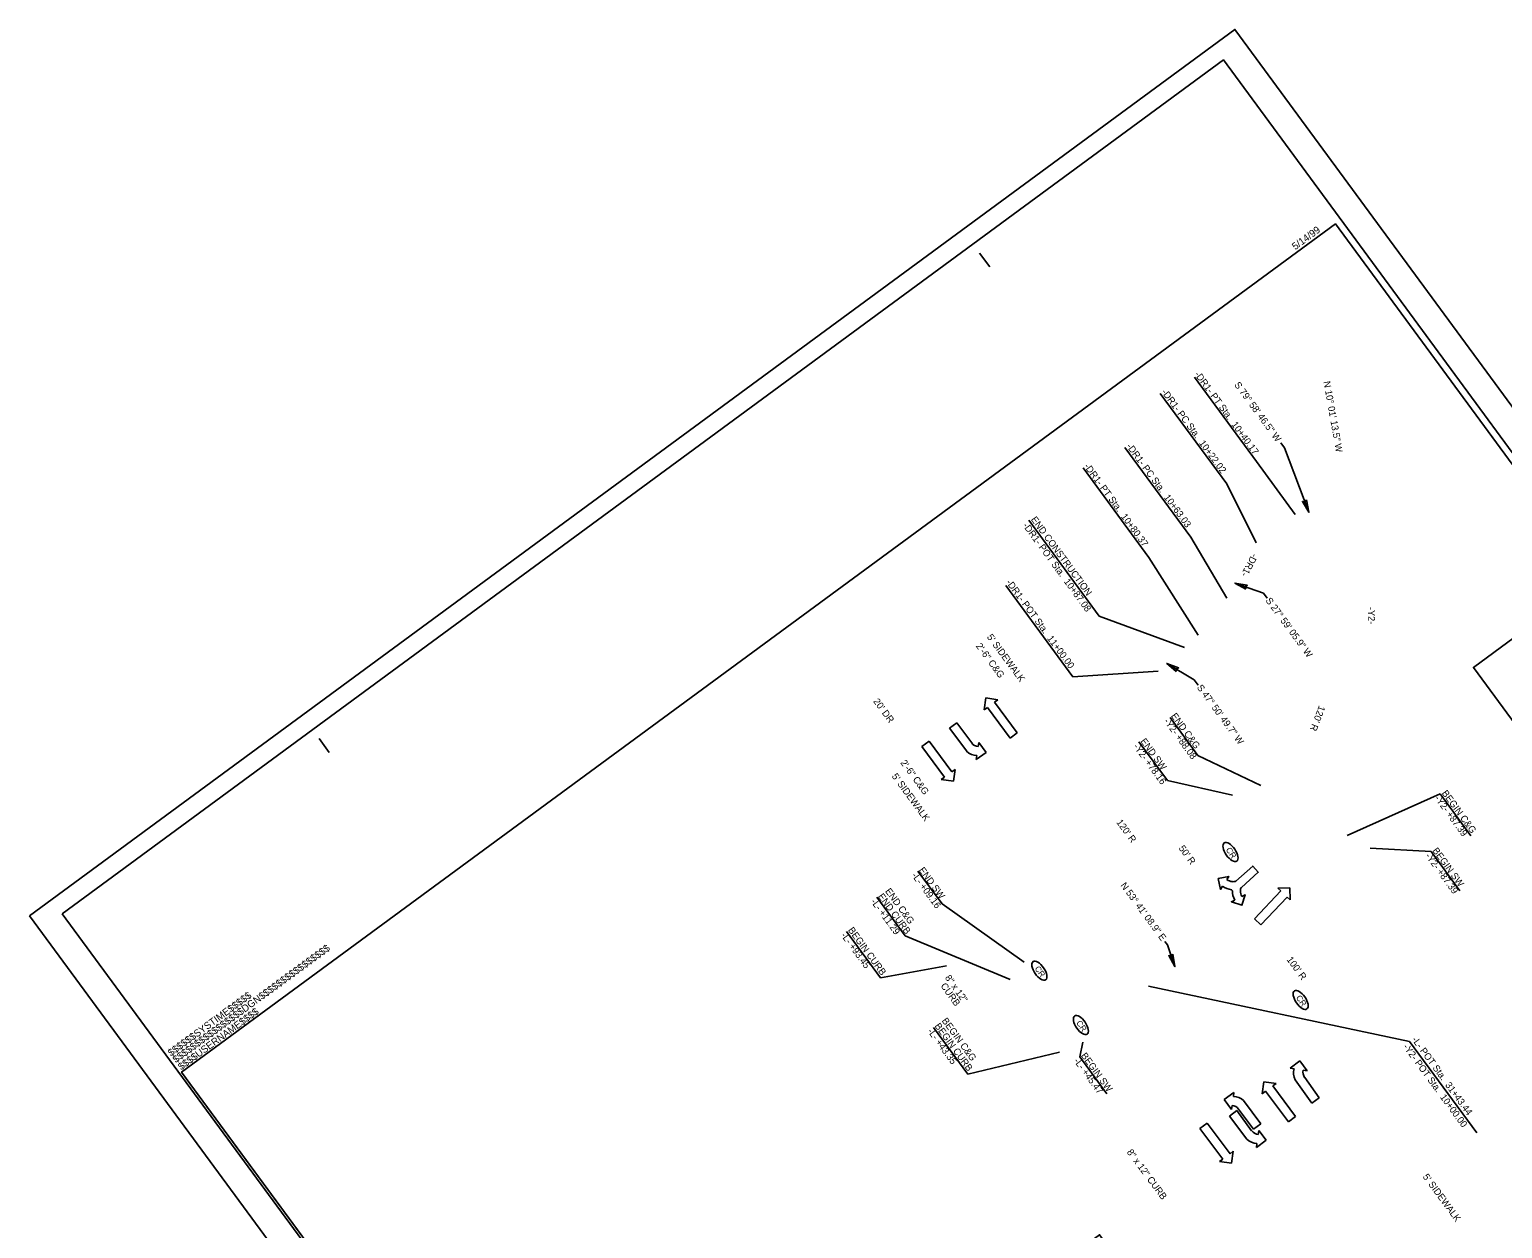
# Model space of a CAD drawing. Extents: x 1763480 to 1764420, y 711010 to 712012.
# Drawn here: x 1763480 to 1764019, y 711573 to 712012 of the extents above; entities that cross this region are included whole.
import ezdxf

# ---------------------------------------------------------------- set-up
doc = ezdxf.new("R2010")
doc.units = 0
for name, color, linetype in [('Old_Level_41', 7, 'Continuous'), ('Old_Level_46', 7, 'Continuous'), ('P-WATER', 7, 'Continuous'), ('Prop Conc 4in Sidewalk', 7, 'Continuous'), ('Prop Grid Mask', 7, 'Continuous'), ('Prop Horizontal Alignment Direction Label', 7, 'Continuous'), ('Prop Horizontal Alignment Station Label', 7, 'Continuous'), ('Prop Lane Arrow CELL', 7, 'Continuous'), ('Prop Rem of Exist Asph Pvmt', 7, 'Continuous'), ('Prop Terminator CELL', 7, 'Continuous'), ('Prop WCC CELL', 7, 'Continuous'), ('Sheet Plot Border Inside CELL', 7, 'Continuous'), ('Sheet Plot Border Outside CELL', 7, 'Continuous')]:
    doc.layers.add(name, color=color, linetype=linetype)

msp = doc.modelspace()

# ---------------------------------------------------------------- linework, layer by layer
at = {"layer": 'Old_Level_41'}
for p, q in [((1763827.54, 711930.36), (1763831.24, 711925.32)), ((1763585.84, 711752.65), (1763589.54, 711747.61))]:
    msp.add_line(p, q, dxfattribs=at)
at = {"layer": 'Old_Level_46'}
msp.add_line((1763980.04, 711910.75), (1763980.04, 711910.75), dxfattribs=at)
at = {"layer": 'P-WATER'}
msp.add_lwpolyline([(1764402.04, 711336.79), (1763957.77, 711941.04), (1763535.55, 711630.61), (1763979.82, 711026.35)], close=True, dxfattribs=at)
at = {"layer": 'Prop Grid Mask'}
for p, q in [((1763907.38, 711746.51), (1763897.22, 711760.38)), ((1763896.24, 711737.35), (1763885.85, 711751.5)), ((1763907.38, 711746.51), (1763930.41, 711735.46)), ((1763896.24, 711737.35), (1763920.14, 711731.96)), ((1763996.13, 711732.42), (1763962.1, 711717.16)), ((1764007.32, 711717.14), (1763996.13, 711732.42)), ((1763970.4, 711712.54), (1763992.74, 711711.38)), ((1764003.32, 711697), (1763992.74, 711711.38)), ((1763813.8, 711692.15), (1763804.99, 711704.14)), ((1763800.27, 711680.54), (1763789.96, 711694.62)), ((1763843.84, 711670.85), (1763813.8, 711692.15)), ((1763791.33, 711665.14), (1763778.89, 711682.12)), ((1763800.27, 711680.54), (1763838.75, 711664.47)), ((1763791.33, 711665.14), (1763815.48, 711669.5)), ((1763823.24, 711629.89), (1763810.72, 711646.99)), ((1763865.35, 711641.6), (1763864.2, 711636.26)), ((1763823.24, 711629.89), (1763856.75, 711637.91)), ((1763874.15, 711622.71), (1763864.2, 711636.26))]:
    msp.add_line(p, q, dxfattribs=at)
at = {"layer": 'Prop Horizontal Alignment Direction Label'}
for q in [(1763895.37, 711678.43), (1763899.02, 711669.24)]:
    msp.add_line((1763896.24, 711677.25), q, dxfattribs=at)
at = {"layer": 'Prop Horizontal Alignment Station Label'}
msp.add_lwpolyline([(1763957.77, 711941.04), (1764052.94, 711811.6), (1764008.24, 711778.74), (1764295.85, 711387.56), (1764241.65, 711347.71), (1764301.88, 711263.14), (1763979.82, 711026.35), (1763792.92, 711280.55), (1763982.56, 711419.98), (1763871.46, 711571.1), (1763681.82, 711431.66), (1763535.55, 711630.61)], close=True, dxfattribs=at)
at = {"layer": 'Prop Lane Arrow CELL'}
for p, q in [((1763829.17, 711763.17), (1763829.79, 711767.54)), ((1763830.38, 711764.06), (1763829.17, 711763.17)), ((1763829.79, 711767.54), (1763834.24, 711766.91)), ((1763838.7, 711752.8), (1763830.38, 711764.06)), ((1763834.24, 711766.91), (1763833.03, 711766.02)), ((1763833.03, 711766.02), (1763841.35, 711754.76)), ((1763819.23, 711758.47), (1763816.57, 711756.52)), ((1763824.65, 711751.1), (1763819.23, 711758.47)), ((1763816.57, 711756.52), (1763822.82, 711748.02)), ((1763841.35, 711754.76), (1763838.7, 711752.8)), ((1763806.42, 711749.81), (1763809.08, 711751.77)), ((1763814.74, 711738.55), (1763806.42, 711749.81)), ((1763809.08, 711751.77), (1763817.4, 711740.51)), ((1763826.33, 711745.01), (1763829.9, 711747.58)), ((1763827.28, 711751.24), (1763827.05, 711749.77)), ((1763829.9, 711747.58), (1763827.28, 711751.24)), ((1763826.55, 711746.48), (1763826.33, 711745.01)), ((1763813.54, 711737.66), (1763814.74, 711738.55)), ((1763817.98, 711737.03), (1763813.54, 711737.66)), ((1763817.4, 711740.51), (1763818.6, 711741.4)), ((1763818.6, 711741.4), (1763817.98, 711737.03)), ((1763921.35, 711700.5), (1763927.5, 711705.99)), ((1763927.5, 711705.99), (1763929.51, 711703.73)), ((1763914.84, 711701.43), (1763918.72, 711702.21)), ((1763915.69, 711697.48), (1763914.84, 711701.43)), ((1763918.72, 711702.21), (1763918.03, 711701.08)), ((1763929.51, 711703.73), (1763923.32, 711698.22)), ((1763916.37, 711698.62), (1763915.69, 711697.48)), ((1763919.72, 711697.36), (1763920.04, 711697)), ((1763924.75, 711695.44), (1763923.5, 711691.71)), ((1763923.55, 711694.89), (1763924.75, 711695.44)), ((1763928.08, 711686.76), (1763937.71, 711696.92)), ((1763940.1, 711694.65), (1763930.47, 711684.49)), ((1763936.62, 711697.95), (1763941.04, 711698.1)), ((1763937.71, 711696.92), (1763936.62, 711697.95)), ((1763941.19, 711693.61), (1763940.1, 711694.65)), ((1763941.04, 711698.1), (1763941.19, 711693.61)), ((1763919.71, 711692.97), (1763920.91, 711693.52)), ((1763923.5, 711691.71), (1763919.71, 711692.97)), ((1763930.47, 711684.49), (1763928.08, 711686.76)), ((1763941.23, 711632.11), (1763944.77, 711634.72)), ((1763944.77, 711634.72), (1763947.44, 711631.1)), ((1763942.69, 711631.87), (1763941.23, 711632.11)), ((1763947.44, 711631.1), (1763945.97, 711631.33)), ((1763930.98, 711622.72), (1763931.59, 711627.1)), ((1763932.19, 711623.62), (1763930.98, 711622.72)), ((1763931.59, 711627.1), (1763936.04, 711626.48)), ((1763940.53, 711612.38), (1763932.19, 711623.62)), ((1763936.04, 711626.48), (1763934.84, 711625.58)), ((1763934.84, 711625.58), (1763943.18, 711614.34)), ((1763949.17, 711619.28), (1763943, 711627.84)), ((1763946.5, 711628.63), (1763951.85, 711621.21)), ((1763920.61, 711623.16), (1763917.05, 711620.58)), ((1763917.05, 711620.58), (1763919.69, 711616.94)), ((1763919.69, 711616.94), (1763919.91, 711618.41)), ((1763920.39, 711621.69), (1763920.61, 711623.16)), ((1763930.43, 711611.71), (1763924.14, 711620.18)), ((1763951.85, 711621.21), (1763949.17, 711619.28)), ((1763921.63, 711616.51), (1763918.98, 711614.54)), ((1763918.98, 711614.54), (1763925.27, 711606.07)), ((1763927.08, 711609.16), (1763921.63, 711616.51)), ((1763922.32, 711617.08), (1763927.78, 711609.74)), ((1763943.18, 711614.34), (1763940.53, 711612.38)), ((1763908.17, 711610.01), (1763910.82, 711611.98)), ((1763916.52, 711598.77), (1763908.17, 711610.01)), ((1763910.82, 711611.98), (1763919.17, 711600.74)), ((1763927.78, 711609.74), (1763930.43, 711611.71)), ((1763929.72, 711609.31), (1763929.5, 711607.84)), ((1763932.4, 711605.7), (1763929.72, 711609.31)), ((1763928.83, 711603.04), (1763932.4, 711605.7)), ((1763929.01, 711604.55), (1763928.83, 711603.04)), ((1763915.31, 711597.88), (1763916.52, 711598.77)), ((1763919.76, 711597.26), (1763915.31, 711597.88)), ((1763919.17, 711600.74), (1763920.37, 711601.63)), ((1763920.37, 711601.63), (1763919.76, 711597.26))]:
    msp.add_line(p, q, dxfattribs=at)
for points in [[(1763923.32, 711698.21), (1763929.51, 711703.73), (1763927.5, 711705.99), (1763921.36, 711700.51)], [(1763918.03, 711701.09), (1763918.72, 711702.21), (1763914.84, 711701.43), (1763915.69, 711697.48), (1763916.37, 711698.62)], [(1763920.01, 711700.32), (1763920.01, 711700.32)], [(1763920.91, 711693.52), (1763919.71, 711692.97), (1763923.5, 711691.71), (1763924.75, 711695.44), (1763923.56, 711694.88)], [(1763919.72, 711697.36), (1763920.04, 711697)], [(1763923.01, 711696.96), (1763923.01, 711696.96)]]:
    msp.add_lwpolyline(points, dxfattribs=at)
for centre, radius, start, end in [((1763826.52, 711751.72), 5.25, 224.9903, 270.302), ((1763827.28, 711753.02), 3.27, 216.3142, 265.9724), ((1763920.41, 711704.3), 4, 233.3311, 264.2613), ((1763920.41, 711704.3), 4, 233.3311, 264.2613), ((1763920.38, 711702.57), 2.28, 260.7712, 295.5372), ((1763920.38, 711702.57), 2.28, 260.7712, 295.5372), ((1763920.41, 711704.3), 6.97, 234.571, 264.2664), ((1763920.41, 711704.3), 6.97, 234.571, 264.2664), ((1763927, 711696.9), 6.97, 179.1348, 208.9876), ((1763927, 711696.9), 6.97, 179.1348, 208.9876), ((1763925.28, 711697.06), 2.28, 149.6269, 182.6249), ((1763925.28, 711697.06), 2.28, 149.6269, 182.6249), ((1763927, 711696.9), 4, 179.1348, 210.3475), ((1763927, 711696.9), 4, 179.1348, 210.3475), ((1763947.67, 711630.22), 5.25, 161.7658, 207.0775), ((1763949.14, 711630.55), 3.27, 166.0954, 215.7536), ((1763919.7, 711615.15), 3.27, 36.5966, 86.2548), ((1763920.45, 711616.45), 5.25, 45.2727, 90.5844), ((1763929.74, 711611.1), 3.28, 216.5966, 266.2548), ((1763928.98, 711609.8), 5.25, 225.2727, 270.5844)]:
    msp.add_arc(centre, radius, start, end, dxfattribs=at)
at = {"layer": 'Prop Rem of Exist Asph Pvmt'}
for p, q in [((1763906.21, 711884.92), (1763928.88, 711854.08)), ((1763893.64, 711878.97), (1763917.98, 711845.86)), ((1763937.79, 711860.94), (1763939.17, 711859.06)), ((1763880.72, 711859.16), (1763904.85, 711826.33)), ((1763939.17, 711859.06), (1763948.02, 711835.52)), ((1763865.38, 711851.77), (1763889.49, 711818.97)), ((1763942.97, 711834.62), (1763928.88, 711854.08)), ((1763928.79, 711824.31), (1763917.98, 711845.86)), ((1763845.59, 711832.59), (1763871.35, 711797.53)), ((1763918.06, 711804.12), (1763904.85, 711826.33)), ((1763907.46, 711790.51), (1763889.49, 711818.97)), ((1763837.13, 711808.64), (1763861.65, 711775.28)), ((1763931.43, 711805.89), (1763920.94, 711809.55)), ((1763931.43, 711805.89), (1763932.81, 711804)), ((1763902.48, 711786.01), (1763871.35, 711797.53)), ((1763906.11, 711774.14), (1763896.04, 711780.18)), ((1763892.9, 711777.34), (1763861.65, 711775.28)), ((1763906.11, 711774.14), (1763907.49, 711772.26)), ((1763889.35, 711662.13), (1763984.88, 711641.88)), ((1764009.5, 711608.39), (1763984.88, 711641.88))]:
    msp.add_line(p, q, dxfattribs=at)
at = {"layer": 'Prop Terminator CELL'}
for points in [[(1763947.16, 711840), (1763948.02, 711835.52), (1763945.68, 711839.47), (1763946.63, 711839.21)], [(1763924.94, 711807.33), (1763920.94, 711809.55), (1763925.48, 711808.81), (1763924.67, 711808.25)], [(1763899.5, 711777.2), (1763896.04, 711780.18), (1763900.33, 711778.54), (1763899.43, 711778.15)], [(1763898.28, 711673.74), (1763899.02, 711669.24), (1763896.78, 711673.25), (1763897.72, 711672.97)]]:
    msp.add_lwpolyline(points, close=True, dxfattribs=at)
at = {"layer": 'Prop WCC CELL'}
for centre in [(1763919.36, 711711.16), (1763849.42, 711667.73), (1763945.03, 711657.05), (1763864.62, 711647.81)]:
    msp.add_ellipse(centre, major_axis=(2.29, -3.33), ratio=0.462467, dxfattribs=at)
at = {"layer": 'Sheet Plot Border Inside CELL'}
msp.add_lwpolyline([(1763491.78, 711688.55), (1763985.22, 711017.43), (1764410.21, 711329.9), (1763916.77, 712001.02)], close=True, dxfattribs=at)
at = {"layer": 'Sheet Plot Border Outside CELL'}
msp.add_lwpolyline([(1763479.87, 711687.86), (1763978.5, 711009.69), (1764419.6, 711334.01), (1763920.98, 712012.18)], close=True, dxfattribs=at)

# ---------------------------------------------------------------- texts
at = {"layer": 'P-WATER'}
for s, p in [('5/14/99', (1763943.04, 711931.36)), ('$$$$$$$$$$$$$$$$DGN$$$$$$$$$$$$$$$$', (1763533.48, 711633.83)), ('$$$$$$SYSTIME$$$$$', (1763531.68, 711636.27)), ('$$$$USERNAME$$$$', (1763535.43, 711631.19))]:
    msp.add_text(s, height=2.625, rotation=36.325, dxfattribs=at).set_placement(p)
at = {"layer": 'Prop Conc 4in Sidewalk'}
for p in [(1763830.08, 711789.81), (1763795.26, 711738.85), (1763989.57, 711592.3)]:
    msp.add_text("5' SIDEWALK", height=2.5, rotation=306.3161, dxfattribs=at).set_placement(p)
at = {"layer": 'Prop Grid Mask'}
for s, rotation, p in [('2\'-6" C&G', 306.2561, (1763826.06, 711786.51)), ("20' DR", 306.325, (1763788.51, 711766.27)), ("120' R", 249.1798, (1763951.78, 711764.94)), ('-Y2- +88.08', 306.2176, (1763894.81, 711759)), ('END C&G', 306.2176, (1763897.43, 711760.92)), ('END SW', 306.3178, (1763886.25, 711751.66)), ('-Y2- +78.16', 306.3178, (1763883.63, 711749.74)), ('2\'-6" C&G', 306.2561, (1763798.44, 711743.8)), ('-Y2- +87.39', 306.2176, (1763993.9, 711730.77)), ('BEGIN C&G', 306.2176, (1763996.52, 711732.69)), ("120' R", 306.332, (1763877.45, 711722)), ("50' R", 306.313, (1763900.26, 711712.5)), ('-Y2- +87.39', 306.3178, (1763990.47, 711709.72)), ('BEGIN SW', 306.3178, (1763993.09, 711711.65)), ('END SW', 306.3178, (1763805.14, 711704.5)), ('-L- +09.16', 306.3178, (1763802.52, 711702.57)), ('END CURB', 306.2176, (1763790.21, 711694.9)), ('END C&G', 306.2176, (1763792.83, 711696.82)), ('-L- +11.29', 306.2176, (1763787.58, 711692.98)), ('BEGIN CURB', 306.2176, (1763779.27, 711682.57)), ('-L- +93.45', 306.2176, (1763776.64, 711680.65)), ("100' R", 306.313, (1763939.77, 711671.78)), ('CURB', 305.4668, (1763813.14, 711662.18)), ('8" x 12"', 305.4668, (1763814.73, 711665.13)), ('BEGIN C&G', 306.2176, (1763813.57, 711649.4)), ('-L- +43.35', 306.2176, (1763808.33, 711645.56)), ('BEGIN CURB', 306.2176, (1763810.95, 711647.48)), ('-L- +45.47', 306.3178, (1763861.86, 711634.68)), ('BEGIN SW', 306.3178, (1763864.48, 711636.61)), ('8" x 12" CURB', 306.4815, (1763881.28, 711601.28))]:
    msp.add_text(s, height=2.5, rotation=rotation, dxfattribs=at).set_placement(p)
at = {"layer": 'Prop Horizontal Alignment Direction Label'}
for s, rotation, p in [('S 79%%d 58\' 46.5" W', 306.313, (1763920.58, 711882.11)), ('N 10%%d 01\' 13.5" W', 280.0204, (1763953.37, 711883.27)), ('-DR1-', 242.015, (1763927.31, 711820.61)), ('S 27%%d 59\' 05.9" W', 306.313, (1763932.06, 711803.17)), ('-Y2-', 270.7727, (1763969.69, 711800.81)), ('S 47%%d 50\' 49.7" W', 306.313, (1763906.91, 711771.34)), ('N 53%%d 41\' 08.9" E', 306.3131, (1763878.96, 711698.92))]:
    msp.add_text(s, height=2.5, rotation=rotation, dxfattribs=at).set_placement(p)
at = {"layer": 'Prop Rem of Exist Asph Pvmt'}
for s, rotation, p in [('-DR1- PT Sta.  10+40.17', 306.313, (1763906.02, 711885.99)), ('-DR1- PC Sta.  10+22.02', 306.313, (1763893.95, 711879.48)), ('-DR1- PC Sta.  10+63.03', 306.313, (1763881.1, 711859.63)), ('-DR1- PT Sta.  10+80.37', 306.313, (1763865.61, 711852.31)), ('END CONSTRUCTION', 306.313, (1763846.2, 711832.83)), ('-DR1- POT Sta.  10+87.08', 306.313, (1763843.18, 711830.61)), ('-DR1- POT Sta.  11+00.00', 306.313, (1763837.06, 711809.82)), ('-Y2- POT Sta.  10+00.00', 306.325, (1763982.35, 711639.84)), ('-L- POT Sta.  31+43.44', 306.325, (1763985.55, 711642.47))]:
    msp.add_text(s, height=2.5, rotation=rotation, dxfattribs=at).set_placement(p)
at = {"layer": 'Prop WCC CELL'}
for p in [(1763917.53, 711711.96), (1763847.58, 711668.52), (1763943.19, 711657.84), (1763862.78, 711648.61)]:
    msp.add_text('CR', height=2.16, rotation=304.4873, dxfattribs=at).set_placement(p)

doc.saveas('drawing.dxf')
